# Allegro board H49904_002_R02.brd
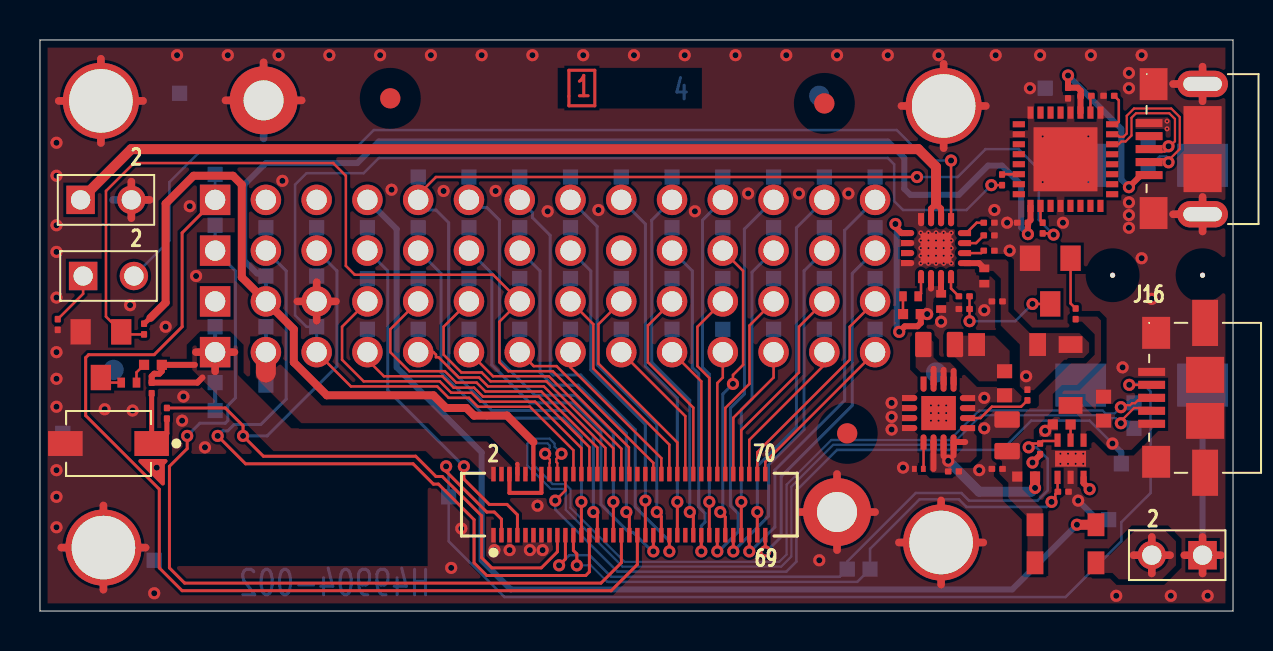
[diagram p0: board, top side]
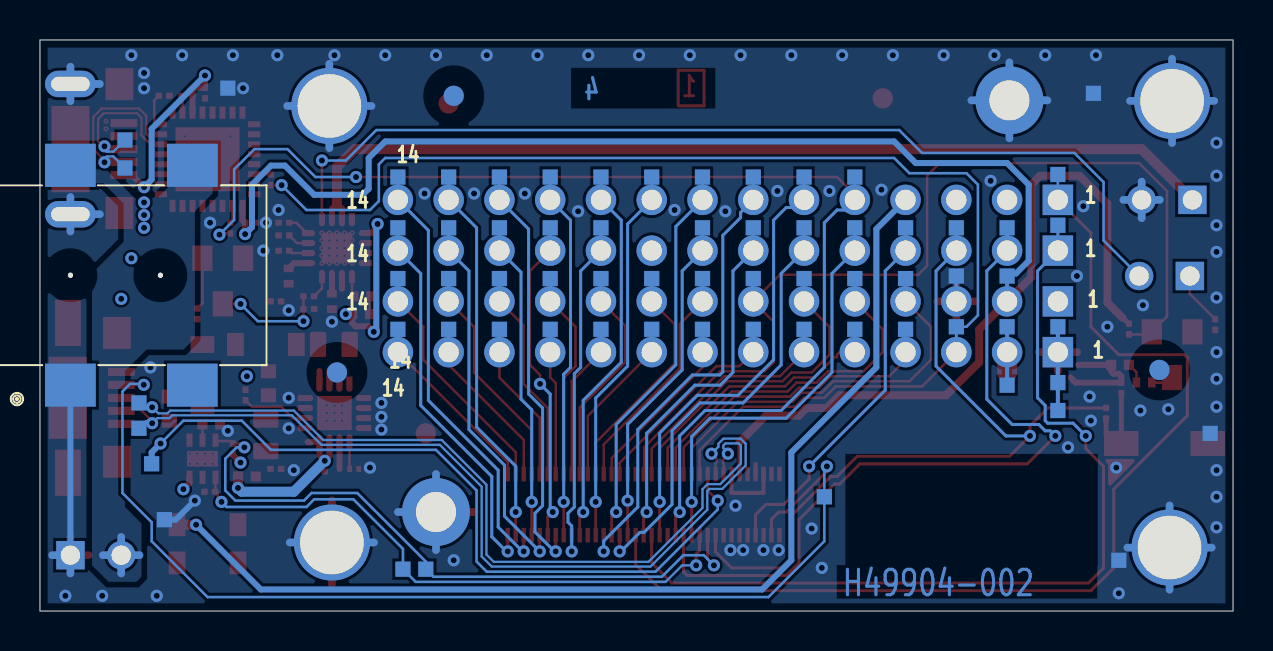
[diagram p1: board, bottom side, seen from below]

Outline 59.69 x 28.57 mm; copper layers: TOP, PWR_GND, GND, BOTTOM. Coordinates in mm from the lower left corner of the outline.
Outline path: 0,28.57 0,0 59.69,0 59.69,28.57 0,28.57

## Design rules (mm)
constraint set DEFAULT: min track width 0.127
net group USB_D: nets USB_DN USB_DP
net group USBD: nets N11374 N11378
net group PWR_GND: nets 5V VBUS_2 VIN

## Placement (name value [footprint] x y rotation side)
C1  22UF  [SMC0603_HI_VALUE]  48.26 12 0 top
C3  0.1uF  [C0201]  45.97 6.99 270 top
C4  33000pF  [SMC0201]  44.2 7.11 270 top
C5  10uF  [SMC0402]  45.09 15.88 0 top
C6  0.1uF  [C0201]  47.62 15.49 90 top
C8  10uF  [SMC0402]  47.24 17.14 0 top
C9  0.1uF  [C0201]  51.44 25.65 180 top
C10  0.1uF  [C0201]  48.9 19.43 90 top
C36  2.2uF  [SMC0603_HI_VALUE]  53.21 9.53 180 top
C47  10uF  [SMC0805]  48.39 8 180 top
C48  0.1uF  [C0201]  53.21 25.78 90 top
CR1  RB160M-40  [SOD123_67X106]  51.56 13.34 0 top
CR2  D2BW319000  [SCR_27X17MA]  48.39 13.34 270 top
CR6  D2BW319000  [SCR_27X17MA]  51.31 4.32 90 top
CR7  D2BW319000  [SCR_27X17MA]  51.31 2.41 90 top
DS1  GREEN  [SMLED0402]  4.06 11.43 90 top
DS3  GREEN  [SMLED0402]  43.94 15.75 270 top
J1  CON2_HDR  [102276-001]  2.16 16.76 90 top
J2  CON2_HDR  [102276-001]  2.03 20.57 90 top
J3  G58911-001  [RCPT_USB_5P_DIP_SM]  58.17 23.11 90 top
J7  70Pin BTB  Socket HIROSE DF40  [2X35_P4MM_BTB_AXT_SKT_MB]  22.69 3.8 0 top
J16  E77884-001  [RCPT_USB_5P_6MTG_SM]  58.29 10.67 90 top
J17  1x14  [1X14RCPT_2P54_VT_TH]  6.22 20.57 0 top
J18  1x14  [1X14RCPT_2P54_VT_TH]  6.22 18.03 0 top
J19  1x14  [1X14RCPT_2P54_VT_TH]  6.22 15.49 0 top
J20  1x14  [1X14RCPT_2P54_VT_TH]  6.22 12.95 0 top
J21  CON2_HDR  [102276-001]  58.17 2.79 270 top
J22  DC_JACK_SMT  [DC_PWR_JACK_SM_14P8X9MM]  58.17 11.3 90 bottom
L1  1uH  [SML0805]  44.2 13.34 90 top
MGT5  NPTH125  [SYMBOL_NPTH125]  45.09 3.43 0 top
MTG1  -  [NPIN787]  11.19 25.55 0 top
MTG2  -  [NPIN787]  39.88 4.95 0 top
MTG3  NPTH125  [SYMBOL_NPTH125]  3.05 25.53 0 top
MTG4  NPTH125  [SYMBOL_NPTH125]  45.21 25.27 0 top
MTG6  NPTH125  [SYMBOL_NPTH125]  3.17 3.17 0 top
NOREF  -  [unnamed]  39.24 25.4 0 top
NOREF#2  -  [#2]  0 27.75 0 top
NOREF#3  -  [#2]  3.17 3.17 0 top
NOREF#4  -  [unnamed]  40.39 8.89 0 top
NOREF#5  -  [#2]  1.73 0 90 top
NOREF#6  -  [unnamed]  17.53 25.65 0 top
NOREF#7  -  [#2]  3.17 3.17 0 top
NOREF#8  -  [unnamed]  38.99 25.78 180 bottom
NOREF#9  -  [unnamed]  3.68 12.06 180 bottom
NOREF#10  -  [unnamed]  44.83 11.94 180 bottom
Q2  BSS138  [SOT23]  51.56 17.65 270 top
Q8  BSS138  [SOT23]  4.06 13.97 270 top
R2  0R  [R0201]  49.4 10.54 180 top
R4  1K  [R0201]  51.82 14.61 180 top
R5  1.62K  [R0201]  46.51 15.75 270 top
R6  1.62K  [R0201]  45.97 15.11 90 top
R7  0R  [R0201]  48.13 21.84 0 top
R8  0R  [R0201]  52.07 25.78 90 top
R9  0R  [R0201]  50.16 19.43 0 top
R36  10K  [SMR0201]  50.04 8.38 0 top
R37  100K  [SMR0201]  50.93 5.97 90 top
R38  576  [SMR0402]  51.56 9.33 270 top
R39  4.7K  [SMR0201]  47.75 19.43 270 top
R48  10K  [SMR0201]  5.59 11.43 0 top
R49  220  [SMR0201]  6.35 10.16 0 top
R72  2K  [SMR0201]  47.75 18.8 270 top
R85  10K  [SMR0201]  5.21 13.84 180 top
R86  576  [SMR0402]  5.21 12.32 90 top
R111  47K  [SMR0201]  47.75 18.03 270 top
R114  576  [SMR0402]  43.18 14.86 90 top
R115  100mOhm  [SMR0402]  48.9 6.73 90 top
R116  10K  [SMR0201]  0.89 14.61 0 top
R117  10K  [SMR0201]  47.62 7.11 90 top
SW1  LIGHT TOUCH SWITCH EVQP7J01P  [SSW2RPB]  3.43 8.38 270 top
TP1  30 MIL TESTPAD  [TP30S]  8.76 11.43 180 bottom
TP2  30 MIL TESTPAD  [TP30S]  50.29 26.16 180 bottom
TP3  30 MIL TESTPAD  [TP30S]  8.76 14.22 180 bottom
TP4  30 MIL TESTPAD  [TP30S]  20.45 5.71 180 bottom
TP5  30 MIL TESTPAD  [TP30S]  8.76 10.03 180 bottom
TP6  30 MIL TESTPAD  [TP30S]  1.14 8.89 180 bottom
TP7  30 MIL TESTPAD  [TP30S]  11.3 11.3 180 bottom
TP8  30 MIL TESTPAD  [TP30S]  16.38 19.18 180 bottom
TP9  30 MIL TESTPAD  [TP30S]  11.3 14.22 180 bottom
TP10  30 MIL TESTPAD  [TP30S]  5.71 2.54 180 bottom
TP11  30 MIL TESTPAD  [TP30S]  11.3 16.76 180 bottom
TP12  30 MIL TESTPAD  [TP30S]  6.99 25.91 180 bottom
TP13  30 MIL TESTPAD  [TP30S]  53.47 4.57 180 bottom
TP14  30 MIL TESTPAD  [TP30S]  54.74 10.41 180 bottom
TP15  30 MIL TESTPAD  [TP30S]  13.84 16.76 180 bottom
TP16  30 MIL TESTPAD  [TP30S]  54.74 9.14 180 bottom
TP17  30 MIL TESTPAD  [TP30S]  13.84 19.18 180 bottom
TP18  30 MIL TESTPAD  [TP30S]  54.1 7.37 180 bottom
TP19  30 MIL TESTPAD  [TP30S]  40.39 2.1 180 bottom
TP20  30 MIL TESTPAD  [TP30S]  13.84 14.22 180 bottom
TP21  30 MIL TESTPAD  [TP30S#2]  41.53 1.33 180 bottom
TP22  30 MIL TESTPAD  [TP30S]  16.38 16.64 180 bottom
TP23  30 MIL TESTPAD  [TP30S]  18.92 19.18 180 bottom
TP24  30 MIL TESTPAD  [TP30S]  16.38 14.1 180 bottom
TP25  30 MIL TESTPAD  [TP30S]  11.3 19.18 180 bottom
TP26  30 MIL TESTPAD  [TP30S]  18.92 16.64 180 bottom
TP27  30 MIL TESTPAD  [TP30S]  18.92 21.72 180 bottom
TP28  30 MIL TESTPAD  [TP30S]  18.92 14.1 180 bottom
TP29  30 MIL TESTPAD  [TP30S]  21.46 16.64 180 bottom
TP30  30 MIL TESTPAD  [TP30S]  21.46 21.72 180 bottom
TP31  30 MIL TESTPAD  [TP30S]  21.46 14.1 180 bottom
TP32  30 MIL TESTPAD  [TP30S]  8.76 19.3 180 bottom
TP33  30 MIL TESTPAD  [TP30S]  24 16.64 180 bottom
TP34  30 MIL TESTPAD  [TP30S]  24 19.18 180 bottom
TP35  30 MIL TESTPAD  [TP30S]  8.76 21.84 180 bottom
TP36  30 MIL TESTPAD  [TP30S]  26.54 19.18 180 bottom
TP37  30 MIL TESTPAD  [TP30S]  21.46 19.18 180 bottom
TP38  30 MIL TESTPAD  [TP30S]  26.54 21.72 180 bottom
TP39  30 MIL TESTPAD  [TP30S]  26.54 16.64 180 bottom
TP40  30 MIL TESTPAD  [TP30S]  24 21.72 180 bottom
TP41  30 MIL TESTPAD  [TP30S]  29.08 16.64 180 bottom
TP42  30 MIL TESTPAD  [TP30S]  29.08 21.72 180 bottom
TP43  30 MIL TESTPAD  [TP30S]  29.08 14.1 180 bottom
TP44  30 MIL TESTPAD  [TP30S]  31.62 16.64 180 bottom
TP45  30 MIL TESTPAD  [TP30S]  31.62 21.72 180 bottom
TP46  30 MIL TESTPAD  [TP30S]  31.62 14.1 180 bottom
TP47  30 MIL TESTPAD  [TP30S]  31.62 19.18 180 bottom
TP48  30 MIL TESTPAD  [TP30S]  34.16 16.64 180 bottom
TP49  30 MIL TESTPAD  [TP30S]  34.16 21.72 180 bottom
TP50  30 MIL TESTPAD  [TP30S]  34.16 14.1 180 bottom
TP51  30 MIL TESTPAD  [TP30S]  36.7 21.72 180 bottom
TP52  30 MIL TESTPAD  [TP30S]  36.7 16.64 180 bottom
TP53  30 MIL TESTPAD  [TP30S]  34.16 19.18 180 bottom
TP54  30 MIL TESTPAD  [TP30S]  36.7 14.1 180 bottom
TP55  30 MIL TESTPAD  [TP30S]  39.24 19.18 180 bottom
TP56  30 MIL TESTPAD  [TP30S]  39.24 16.64 180 bottom
TP57  30 MIL TESTPAD  [TP30S]  36.7 19.18 180 bottom
TP58  30 MIL TESTPAD  [TP30S]  39.24 14.1 180 bottom
TP59  30 MIL TESTPAD  [TP30S]  41.78 21.72 180 bottom
TP60  30 MIL TESTPAD  [TP30S]  41.78 16.64 180 bottom
TP61  30 MIL TESTPAD  [TP30S]  39.24 21.72 180 bottom
TP62  30 MIL TESTPAD  [TP30S]  41.78 14.1 180 bottom
TP63  30 MIL TESTPAD  [TP30S]  41.78 19.18 180 bottom
TP85  30 MIL TESTPAD  [TP30S]  55.44 22.17 0 bottom
TP86  30 MIL TESTPAD  [TP30S]  55.44 23.57 0 bottom
TP87  30 MIL TESTPAD  [TP30S]  26.54 14.1 180 bottom
TP88  30 MIL TESTPAD  [TP30S]  24 14.1 180 bottom
U1  BQ24074  [LCC16_3X3MM_EP61]  44.83 18.16 270 top
U2  FT232R  [LCC32_P5MM_3P2SQ_NONC]  51.31 22.61 90 top
U36  MIC2039  [DFN6P_65M_2X2M]  51.56 7.62 270 top
U37  TPS62133  [LCC16_3X3MM_67DIE_39H]  44.96 9.91 270 top

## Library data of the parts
C1 = CAPC,X5R,0603,6.3V,20%,22UF
C3 C6 C9 C10 C48 = CAP
C4 = CAPC,X5R,0201,6.3V,10%,33000pF
C5 C8 = CAPC,X5R,0402,6.3V,20%,10uF: tolerance: 20%
C36 = CAPC,X5R,0603,25V,10%,2.2uF: tolerance: 10%; room: USB
C47 = CAPC,X7R,0805,50V,10%,1.0uF: tolerance: 10%
CR1 = DIO,SHTKY,SOD123,RB160M-40
CR2 CR6 CR7 = DIO,SHTKY,DB2W319000L
DS1 DS3 = LED,SMT,GREEN,V,0402
J1 J2 J21 = CON2,HDR,TH,0.1in,A91829-020
J3 J16 = CON4,USB,RA,_1
J7 = CON70,SKT,SM,4mm,AXT570124_0: room: NO_ROOM
J17-J20 = CON14,1X14,0.1,0.093: room: NO_ROOM
J22 = CON3,Pwr-Jack,SMT,KLDX-2mm
L1 = INDCT,1uH,1.1A,30%,0805: tolerance: 30%; room: NO_ROOM
MGT5 MTG3 MTG4 MTG6 = symbol_npth125_0
MTG1 MTG2 = MOUNTING HOLE 787
Q2 Q8 = XSTR,BSS138,FET,NCH,SOT23
R2 R7-R9 = R_0
R4-R6 = R0603
R36 R85 R116 R117 = RESD,0201,5%,1/20W,10K: tolerance: 5%; room: AUDIO_CODEC
R37 = RESD,0201,5%,1/20W,100K: tolerance: 5%; room: APE_PMIC_MISC
R38 R86 R114 = RESD,0201,1%,1/20W,562: tolerance: 1%
R39 = RESD,0201,5%,1/20W,4.7K: tolerance: 5%; room: APE_PMIC_MISC
R48 = RESD,0201,5%,1/20W,10K: tolerance: 5%; room: USB
R49 = RESD,0201,5%,1/20W,220: tolerance: 5%; room: UI_BUTTONS
R72 = RESD,0201,1%,1/20W,2K: tolerance: 1%; room: APE_PMIC_MISC
R111 = RESD,0201,1%,1/20W,47K: tolerance: 1%
R115 = RESD,0402,1%,1/16W,100mOhm: tolerance: 1%
SW1 = SWITCH,EVQP7J01P,4P,PWR_0: room: UI_BUTTONS
TP1-TP63 TP85-TP88 = TestPad,C80,SMT: room: TEST_APE
U1 = IC,BQ24232,QFN16,USB_CHGR
U2 = FT232R_0
U36 = IC,MIC2039,UsbPwrSwtch_0: User Part Number: H40907-001; Tolerance: XXX; room: NO_ROOM
U37 = TPS62133_0

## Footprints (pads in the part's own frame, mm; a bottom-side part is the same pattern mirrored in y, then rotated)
1X14RCPT_2P54_VT_TH
  rect 1.524x1.524 hole 1.016: 1(2.54,0)
  round 1.524 hole 1.016: 2(5.08,0) 3(7.62,0) 4(10.16,0) 5(12.7,0) 6(15.24,0) 7(17.78,0) 8(20.32,0) 9(22.86,0) 10(25.4,0) 11(27.94,0) 12(30.48,0) 13(33.02,0) 14(35.56,0)
2X35_P4MM_BTB_AXT_SKT_MB
  rect 0.22x0.728 smd: 1(0,0) 2(0,3.058) 3(0.4,0) 4(0.4,3.058) 5(0.8,0) 6(0.8,3.058) 7(1.2,0) 8(1.2,3.058) 9(1.6,0) 10(1.6,3.058) 11(2,0) 12(2,3.058) 13(2.4,0) 14(2.4,3.058) 15(2.8,0) 16(2.8,3.058) 17(3.2,0) 18(3.2,3.058) 19(3.6,0) 20(3.6,3.058) 21(4,0) 22(4,3.058) 23(4.4,0) 24(4.4,3.058) 25(4.8,0) 26(4.8,3.058) 27(5.2,0) 28(5.2,3.058) 29(5.6,0) 30(5.6,3.058) 31(6,0) 32(6,3.058) 33(6.4,0) 34(6.4,3.058) 35(6.8,0) 36(6.8,3.058) 37(7.2,0) 38(7.2,3.058) 39(7.6,0) 40(7.6,3.058) 41(8,0) 42(8,3.058) 43(8.4,0) 44(8.4,3.058) 45(8.8,0) 46(8.8,3.058) 47(9.2,0) 48(9.2,3.058) 49(9.6,0) 50(9.6,3.058) 51(10,0) 52(10,3.058) 53(10.4,0) 54(10.4,3.058) 55(10.8,0) 56(10.8,3.058) 57(11.2,0) 58(11.2,3.058) 59(11.6,0) 60(11.6,3.058) 61(12,0) 62(12,3.058) 63(12.4,0) 64(12.4,3.058) 65(12.8,0) 66(12.8,3.058) 67(13.2,0) 68(13.2,3.058) 69(13.6,0) 70(13.6,3.058)
102276-001
  rect 1.422x1.422 hole 0.965: 1(0,0)
  round 1.422 hole 0.965: 2(0,-2.54)
C0201
  custom 0.076x0.076 smd: 1(0,0) 2(0,-0.533)
DC_PWR_JACK_SM_14P8X9MM
  round 0.254 hole 1.803 unplated: (5.5,-4.5)
  round 0.254 hole 1.6 unplated: (5.501,0)
  rect 2.159x2.54 smd: 1(0,0) 2(0,-6.1) 3(11,0) 4(11,-6.1)
DFN6P_65M_2X2M
  rect 0.66x0.305 smd: 1(-0.93,0.65) 2(-0.93,0) 3(-0.93,-0.65) 4(0.93,-0.65) 5(0.93,0) 6(0.93,0.65)
  rect 0.787x1.549 smd: 7(0,0)
LCC16_3X3MM_67DIE_39H
  custom 0.076x0.076 smd: 1(-1.448,0.752) 2(-1.448,0.252) 3(-1.448,-0.249) 4(-1.448,-0.749) 5(-0.752,-1.448) 6(-0.252,-1.448) 7(0.249,-1.448) 8(0.749,-1.448) 9(1.448,-0.752) 10(1.448,-0.252) 11(1.448,0.249) 12(1.448,0.749) 13(0.752,1.448) 14(0.252,1.448) 15(-0.249,1.448) 16(-0.749,1.448)
  rect 1.702x1.702 smd: 17(0,0)
LCC16_3X3MM_EP61
  custom 0.076x0.076 smd: 1(-1.422,0.752) 2(-1.422,0.252) 3(-1.422,-0.249) 4(-1.422,-0.749) 5(-0.752,-1.422) 6(-0.252,-1.422) 7(0.249,-1.422) 8(0.749,-1.422) 9(1.422,-0.752) 10(1.422,-0.252) 11(1.422,0.249) 12(1.422,0.749) 13(0.752,1.422) 14(0.252,1.422) 15(-0.249,1.422) 16(-0.749,1.422)
  rect 1.549x1.549 smd: 17(0,0)
LCC32_P5MM_3P2SQ_NONC
  rect 0.61x0.305 smd: 1(-2.334,1.75) 2(-2.334,1.25) 3(-2.334,0.749) 4(-2.334,0.252) 5(-2.334,-0.249) 6(-2.334,-0.749) 7(-2.334,-1.25) 8(-2.334,-1.75) 17(2.334,-1.75) 18(2.334,-1.25) 19(2.334,-0.749) 20(2.334,-0.252) 21(2.334,0.249) 22(2.334,0.749) 23(2.334,1.25) 24(2.334,1.75)
  rect 0.305x0.61 smd: 9(-1.75,-2.334) 10(-1.25,-2.334) 11(-0.749,-2.334) 12(-0.252,-2.334) 13(0.249,-2.334) 14(0.749,-2.334) 15(1.25,-2.334) 16(1.75,-2.334) 25(1.75,2.334) 26(1.25,2.334) 27(0.749,2.334) 28(0.252,2.334) 29(-0.249,2.334) 30(-0.749,2.334) 31(-1.25,2.334) 32(-1.75,2.334)
  rect 3.2x3.2 smd: 33(0,0)
NPIN787
  round 3.4 hole 2: 1(0,0)
R0201
  custom 0.076x0.076 smd: 1(0,0) 2(0,-0.533)
RCPT_USB_5P_6MTG_SM
  rect 0.406x1.346 smd: 1(-1.3,2.675) 2(-0.65,2.675) 3(0,2.675) 4(0.65,2.675) 5(1.3,2.675)
  rect 1.803x1.905 smd: MT1(-1.15,0) MT2(1.15,0)
  rect 2.311x1.295 smd: MT3(-3.75,0) MT4(3.75,0)
  rect 1.6x1.397 smd: MT5(-3.2,2.45) MT6(3.25,2.45)
RCPT_USB_5P_DIP_SM
  rect 0.406x1.346 smd: 1(-1.3,2.675) 2(-0.65,2.675) 3(0,2.675) 4(0.65,2.675) 5(1.3,2.675)
  rect 1.905x1.905 smd: MT1(-1.201,0) MT2(1.201,0)
  oval 1.321x2.54 hole 0.711x1.93: MT3(-3.26,0) MT4(3.26,0)
  rect 1.6x1.397 smd: MT5(-3.2,2.45) MT6(3.25,2.45)
SCR_27X17MA
  rect 1.143x0.838 smd: 1(0,1.525) 2(0,-1.525)
SMC0201
  custom 0.06x0.06 smd: 1(0,0) 2(0,-0.451)
SMC0402
  custom 0.095x0.095 smd: 1(0,0) 2(0,-0.766)
SMC0603_HI_VALUE
  custom 0.175x0.175 smd: 1(0,0) 2(0,-1.204)
SMC0805
  custom 0.204x0.204 smd: 1(0,0) 2(0,-1.581)
SML0805
  custom 0.204x0.204 smd: 1(0,0) 2(0,-1.581)
SMLED0402
  custom 0.095x0.095 smd: 1(0,0) 2(0,-0.766)
SMR0201
  custom 0.076x0.076 smd: 1(0,0) 2(0,-0.533)
SMR0402
  custom 0.127x0.127 smd: 1(0,0) 2(0,-0.889)
SOD123_67X106
  rect 1.194x0.838 smd: 1(0,0) 2(0,-3.048)
SOT23
  custom 0.254x0.254 smd: 1(0,0) 2(0,-2.032) 3(2.286,-1.016)
SSW2RPB
  rect 1.245x1.727 smd: 1(0,2.159) 2(0,-2.159)
SYMBOL_NPTH125
  round 3.81 hole 3.18: 1(0,0)
TP30S
  rect 0.762x0.762 smd: 1(0,0)
TP30S#2
  rect 0.762x0.762 smd: 1(0,0.762)
unnamed
  round 1.016 smd: (0,0)

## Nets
5V: J19.1
5V_SYS: C6.2(END2) C8.1 CR1.1(CATHODE) CR2.1(CATHODE) R2.2 U1.13(IN) U36.6(VIN)
GND: C1.2 C3.1(END1) C4.2 C5.2 C6.1(END1) C8.2 C9.1(END1) C10.1(END1) C36.2 C47.2 C48.1(END1) J2.2 J3.5(GND) J3.MT1 J3.MT2 J3.MT3 J3.MT4 J3.MT5 J3.MT6 J7.1 J7.5 J7.9 J7.11 J7.13 J7.15 J16.5(GND) J16.MT1 J16.MT2 J16.MT3 J16.MT4 J16.MT5 J16.MT6 J19.3 J21.1 J22.1(GND) MGT5.1 MTG1.1 MTG2.1 MTG3.1 MTG4.1 MTG6.1 Q2.2(S) Q8.2(S) R6.1 R37.2 R38.2 R39.1 R72.1 R111.1 R116.2 R117.1 SW1.2(B) TP2.1 TP6.1 TP10.1 TP12.1 TP13.1 TP15.1 U1.4(C\E\) U1.6(EN1) U1.8(VSS) U1.17(TPAD) U2.4(GND3) U2.17(GND1) U2.20(GND2) U2.24(AGND) U2.26(TEST) U2.33(TPAD) U36.5(GND) U36.7(TPAD) U37.5(FB) U37.6(AGND) U37.7(FSW) U37.8(DEF) U37.15(PGND1) U37.16(PGND2) U37.17(THPAD)
VBUS: C36.1 CR1.2(ANODE) J7.20 J16.1(VCC) TP18.1 U36.1(VOUT)
VBUS_2: C9.2(END2) J3.1(VCC) R8.1 U2.19(VCC)
VIN: CR6.2(ANODE) J17.4
FAULT: J7.19 R36.1 TP19.1 U36.3(F\A\U\L\T\)
FW_RCVR: J7.69 J18.14 TP63.1
GP12_PWM0: J7.35 J18.7 TP34.1
GP13_PWM1: J7.33 J18.1 TP32.1
GP14: J7.48 J19.9 TP41.1
GP15: J7.42 J20.7 TP88.1
GP19: J7.41 J18.6 TP37.1
GP20: J7.43 J17.8 TP38.1
GP27: J7.45 J17.7 TP40.1
GP28: J7.47 J17.9 TP42.1
GP40: J7.52 J19.10 TP44.1
GP41: J7.54 J20.10 TP46.1
GP42: J7.50 J20.9 TP43.1
GP43: J7.56 J19.11 TP48.1
GP44: J7.24 J19.4 TP22.1
GP45: J7.26 J20.4 TP24.1
GP46: J7.28 J19.5 TP26.1
GP47: J7.30 J20.5 TP28.1
GP48: J7.32 J19.6 TP29.1
GP49: J7.34 J20.6 TP31.1
GP77: J7.60 J19.12 TP52.1
GP78: J7.58 J20.11 TP50.1
GP79: J7.62 J20.12 TP54.1
GP80: J7.66 J20.13 TP58.1
GP81: J7.70 J20.14 TP62.1
GP82: J7.64 J19.13 TP56.1
GP83: J7.68 J19.14 TP60.1
GP84: J7.44 J20.8 TP87.1
GP109: J7.55 J17.11 TP49.1
GP110: J7.53 J18.10 TP47.1
GP111: J7.51 J17.10 TP45.1
GP114: J7.59 J18.11 TP53.1
GP115: J7.57 J17.12 TP51.1
GP128: J7.65 J17.14 TP59.1
GP129: J7.63 J18.12 TP57.1
GP130: J7.61 J18.13 TP55.1
GP131: J7.46 J19.8 TP39.1
GP134: J7.22 J20.3 R7.2 TP20.1
GP135: J7.27 J17.5 R9.2 TP27.1
GP165: J7.25 J18.2 TP25.1
GP182_PWM2: J7.37 J17.1 TP35.1
GP183_PWM3: J7.39 J18.8 TP36.1
GPI_PWRBTN_N: J7.17 J18.3 R49.1 TP17.1
GPI_PWRBTN_N_L: R48.2 R49.2 SW1.1(A)
MSIC_SLPCLK_2: J7.7 J18.4 TP8.1
OSC_CLK_OUT_0: J7.67 J17.13 TP61.1
PSW: J7.21 R37.1 TP21.1 U36.4(EN)
RCVR_MODE: J7.31 J17.6 TP30.1
RESETOUT#: J7.36 J19.7 Q8.1(G) R85.1 TP33.1
USB_DN: J7.18 J16.2(USB-) TP16.1
USB_DP: J7.16 J16.3(USB+) TP14.1
USB_ID: J7.3 J16.4(ID) TP4.1
V_1P80: C10.2(END2) J7.12 J19.2 R36.2 R85.2 TP11.1 U2.1(VCCIO)
V_3P30: J7.8 J7.10 J20.2 TP7.1 TP9.1
V_SYS: C5.1 J7.2 J7.4 J7.6 J7.14 J20.1 R48.1 R86.2 R114.2 TP1.1 TP3.1 TP5.1 U1.5(EN2) U1.10(OUT2) U1.11(OUT1)
V_VBAT_BKUP: J7.23 J18.5 TP23.1
N11374: J3.2(USB-) TP85.1 U2.15(USBDM)
N11378: J3.3(USB+) TP86.1 U2.14(USBDP)
N30036849: R8.2 U2.18(R\E\S\E\T)
N30112835: R38.1 U36.2(ILIM)
N30125838: R7.1 U2.30(TXD)
N30125857: R9.1 U2.2(RXD)
N30202561: DS1.1(LED1) Q8.3(D)
N30202678: DS1.2(LED2) R86.1
N30230113: C48.2(END2) U2.16(3V3OUT)
N30332540: C47.1 CR6.1(CATHODE) CR7.1(CATHODE) R4.1 R115.1 R117.2
N30332593: CR7.2(ANODE) J21.2 J22.3(IN_2) J22.4(IN_1)
N30352182: J2.1 U1.2(BAT1) U1.3(BAT2)
N30352285: DS3.1(LED1) U1.9(\\C\H\R\G\)
N30352331: DS3.2(LED2) R114.1
N30352588: J1.2 U1.1(TS)
N30354262: R39.2 U1.16(ISET)
N30354335: R72.2 U1.15(ITERM)
N30354821: R111.2 U1.14(TMR)
N30354968: Q2.3(D) R5.1 R6.2
N30354976: Q2.1(G) R4.2
N30355044: R5.2 U1.12(ILIM)
N30364668: J1.1 R116.1
N30367578: C3.2(END2) R115.2 U37.10(AVIN) U37.11(PVIN2) U37.12(PVIN1) U37.13(EN)
N30367602: C4.1 U37.9(SS/TR)
N30367634: L1.1 U37.1(SW1) U37.2(SW2) U37.3(SW3)
N30367646: C1.1 CR2.2(ANODE) L1.2
N30367678: R2.1 U37.14(VOS)

Pads without a net: J3 4; J7 29 38 40 49; J17 2 3; J18 9; J22 2; U1 7; U2 3 5 6 7 8 9 10 11 12 13 21 22 23 25 27 28 29 31 32; U37 4

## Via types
v1: diameter 0.61, hole 0.305, TOP to BOTTOM, 143 vias
v2: diameter 0.254, hole 0.102, TOP to PWR_GND, 48 vias

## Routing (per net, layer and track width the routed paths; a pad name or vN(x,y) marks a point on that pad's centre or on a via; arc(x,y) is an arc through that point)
5V_SYS: length 1.8
  TOP w0.3: U1.13 46.98,17.41 C8.1 ; v1(52.51,6.1) 52.21,6.4 U36.6
  vias: v1(49.34,11.75)
GND: length 260.1
  TOP w0.381: 3.05,23.42 MTG3.1 ; MTG3.1 5.16,25.53 ; MTG3.1 3.05,27.64 ; MTG3.1 0.94,25.53 ; 39.88,3.05 MTG2.1 ; MTG2.1 41.78,4.95 ; MTG2.1 39.88,6.86 ; MTG2.1 37.97,4.95 ; 13.84,14.53 J19.3 ; J19.3 12.88,15.49 ; J19.3 13.84,16.46 ; J19.3 14.81,15.49 ; J21.1 58.17,3.71 ; J21.1 58.17,1.88 ; J21.1 59.08,2.79 ; J21.1 57.25,2.79 ; 1.07,3.17 MTG6.1 ; MTG6.1 3.17,1.07 ; MTG6.1 5.28,3.17 ; MTG6.1 3.17,5.28 ; 42.98,3.43 MGT5.1 ; MGT5.1 47.19,3.43 ; MGT5.1 45.09,1.32 ; MGT5.1 45.09,5.54 ; MTG1.1 13.09,25.55 ; MTG1.1 9.28,25.55 ; MTG1.1 11.19,27.46 ; J3.MT3 58.17,20.72 ; J3.MT3 56.69,19.85 ; J3.MT3 58.17,18.99 ; 4.57,19.66 J2.2 ; J2.2 4.57,21.49 ; J2.2 5.49,20.57 ; 45.21,23.16 MTG4.1 ; MTG4.1 43.1,25.27 ; MTG4.1 45.21,27.38 ; MTG4.1 47.32,25.27 ; 58.17,25.51 J3.MT4 ; J3.MT4 56.69,26.37 ; J3.MT4 58.17,27.24
  PWR_GND w0.381: 57.25,2.79 J21.1 ; J21.1 59.08,2.79 ; J21.1 58.17,1.88 ; J21.1 58.17,3.71 ; MTG2.1 39.88,6.66 ; MTG2.1 39.88,3.24 ; MTG2.1 41.59,4.95 ; MTG2.1 38.17,4.95 ; J3.MT3 58.17,20.72 ; J3.MT3 58.17,18.99 ; J3.MT3 56.69,19.85 ; 4.57,19.66 J2.2 ; J2.2 5.49,20.57 ; J2.2 4.57,21.49 ; J2.2 3.66,20.57 ; MTG3.1 5.16,25.53 ; MTG3.1 0.94,25.53 ; MTG3.1 3.05,27.64 ; MTG3.1 3.05,23.42 ; 45.21,23.16 MTG4.1 ; MTG4.1 47.32,25.27 ; MTG4.1 45.21,27.38 ; MTG4.1 43.1,25.27 ; J19.3 13.84,16.46 ; J19.3 12.88,15.49 ; J19.3 14.81,15.49 ; J19.3 13.84,14.53 ; 1.07,3.17 MTG6.1 ; MTG6.1 5.28,3.17 ; MTG6.1 3.17,5.28 ; MTG6.1 3.17,1.07 ; MGT5.1 45.09,5.54 ; MGT5.1 45.09,1.32 ; MGT5.1 42.98,3.43 ; MGT5.1 47.19,3.43 ; J3.MT4 58.17,27.24 ; J3.MT4 56.69,26.37 ; J3.MT4 58.17,25.51 ; MTG1.1 12.9,25.55 ; MTG1.1 9.48,25.55 ; MTG1.1 11.19,23.84 ; MTG1.1 11.19,27.26
  GND w0.381: 3.66,20.57 J2.2 ; J2.2 5.49,20.57 ; J2.2 4.57,19.66 ; J2.2 4.57,21.49 ; MTG1.1 12.9,25.55 ; MTG1.1 11.19,27.26 ; MTG1.1 11.19,23.84 ; MTG1.1 9.48,25.55 ; MGT5.1 45.09,5.54 ; MGT5.1 42.98,3.43 ; MGT5.1 45.09,1.32 ; MGT5.1 47.19,3.43 ; 13.84,14.53 J19.3 ; J19.3 12.88,15.49 ; J19.3 14.81,15.49 ; J19.3 13.84,16.46 ; 0.94,25.53 MTG3.1 ; MTG3.1 3.05,23.42 ; MTG3.1 3.05,27.64 ; MTG3.1 5.16,25.53 ; MTG6.1 3.17,5.28 ; MTG6.1 3.17,1.07 ; MTG6.1 1.07,3.17 ; MTG6.1 5.28,3.17 ; MTG2.1 41.59,4.95 ; MTG2.1 39.88,6.66 ; MTG2.1 39.88,3.24 ; MTG2.1 38.17,4.95 ; 45.21,23.16 MTG4.1 ; MTG4.1 47.32,25.27 ; MTG4.1 43.1,25.27 ; MTG4.1 45.21,27.38 ; 57.25,2.79 J21.1 ; J21.1 59.08,2.79 ; J21.1 58.17,1.88 ; J21.1 58.17,3.71 ; J3.MT3 58.17,20.72 ; J3.MT3 58.17,18.99 ; J3.MT3 56.69,19.85 ; J3.MT4 58.17,27.24 ; J3.MT4 56.69,26.37 ; J3.MT4 58.17,25.51
  BOTTOM w0.2: J19.3 TP15.1
  BOTTOM w0.3: J22.1 J21.1 ; TP13.1 52.9,4.57 v1(51.94,5.52)
  BOTTOM w0.381: 42.98,3.43 MGT5.1 47.19,3.43 ; 3.05,23.42 MTG3.1 ; MTG3.1 3.05,27.64 ; MTG3.1 5.16,25.53 ; MTG3.1 0.94,25.53 ; 45.21,23.16 MTG4.1 ; MTG4.1 43.1,25.27 ; MTG4.1 45.21,27.38 ; MTG4.1 47.32,25.27 ; MTG6.1 5.28,3.17 ; MTG6.1 1.07,3.17 ; MTG6.1 3.17,5.28 ; MTG6.1 3.17,1.07 ; J3.MT4 58.17,27.24 ; J3.MT4 56.69,26.37 ; J3.MT4 58.17,25.51 ; J2.2 5.49,20.57 ; J2.2 3.66,20.57 ; J2.2 4.57,19.66 ; J2.2 4.57,21.49 ; MTG1.1 11.19,27.46 ; MTG1.1 11.19,23.65 ; MTG1.1 13.09,25.55 ; MTG1.1 9.28,25.55 ; 59.08,2.79 J21.1 58.17,1.88 ; MTG2.1 39.88,6.86 ; MTG2.1 39.88,3.05 ; MTG2.1 41.78,4.95 ; 58.17,18.99 J3.MT3 ; J3.MT3 56.69,19.85 ; J3.MT3 58.17,20.72
  vias: v1(0.83,23.43) v1(0.83,21.78) v1(0.83,19.3) v1(0.83,17.97) v1(0.83,15.68) v1(0.83,12.95) v1(0.83,11.62) v1(0.83,10.22) v1(0.83,7.05) v1(0.83,5.71) v1(0.83,4.19) v1(3.24,10.1) v1(4.51,15.3) v1(4.64,10.03) v1(5.71,0.89) v1(5.84,7.18) v1(6.29,14.22) v1(6.86,27.81) v1(7.11,9.53) v1(7.18,10.73) v1(7.49,20.26) v1(7.81,16.76) v1(8.26,8.19) v1(9.4,27.81) v1(11.94,27.81) v1(12.13,21.53) v1(14.48,27.81) v1(17.02,27.81) v1(17.59,21.08) v1(19.56,27.81) v1(20.19,21.02) v1(20.57,2.16) v1(21.08,4.13) v1(22.1,27.81) v1(22.73,3.05) v1(22.8,21.02) v1(23.5,3.05) v1(24.51,3.05) v1(24.64,27.81) v1(24.89,5.27) v1(25.15,3.05) v1(25.4,20) v1(27.18,27.81) v1(27.94,20.07) v1(29.72,27.81) v1(32.26,27.81) v1(32.77,20) v1(34.8,27.81) v1(35.43,20.89) v1(37.34,27.81) v1(37.97,20.89) v1(38.99,2.54) v1(39.88,27.81) v1(40.45,20.89) v1(42.42,27.81) v1(42.61,10.41) v1(42.61,9.72) v1(42.61,9.08) v1(43.18,7.18) v1(44.96,27.81) v1(45.09,14.48) v1(46.99,7.05) v1(47.24,15.05) v1(47.24,10.67) v1(47.24,9.14) v1(47.82,27.81) v1(47.75,20.07) v1(48.39,19.43) v1(48.51,18.03) v1(49.53,26.16) v1(50.04,27.81) v1(50.29,9.02) v1(51.18,19.43) v1(52.58,27.81) v1(53.85,0.76) v1(54.17,12.19) v1(54.48,26.92) v1(54.48,26.16) v1(54.48,20.45) v1(54.48,19.81) v1(54.48,19.18) v1(55.12,27.81) v1(55.12,17.65) v1(55.63,15.62) v1(56.58,0.76) v1(58.42,0.76) v2(44.07,18.92) v2(44.07,18.54) v2(44.07,18.16) v2(44.07,17.78) v2(44.07,17.4) v2(44.45,18.92) v2(44.45,18.54) v2(44.45,18.16) v2(44.45,17.78) v2(44.45,17.4) v2(44.58,10.29) v2(44.58,9.91) v2(44.58,9.53) v2(44.83,18.92) v2(44.83,18.54) v2(44.83,18.16) v2(44.83,17.78) v2(44.83,17.4) v2(44.96,10.29) v2(44.96,9.91) v2(44.96,9.53) v2(45.21,18.92) v2(45.21,18.54) v2(45.21,18.16) v2(45.21,17.78) v2(45.21,17.4) v2(45.34,10.29) v2(45.34,9.91) v2(45.34,9.53) v2(45.59,18.92) v2(45.59,18.54) v2(45.59,18.16) v2(45.59,17.78) v2(45.59,17.4) v2(50.16,23.75) v2(50.16,21.46) v2(51.05,7.87) v2(51.05,7.37) v2(51.44,7.87) v2(51.44,7.37) v2(51.82,7.87) v2(51.82,7.37) v2(52.2,7.87) v2(52.2,7.37) v2(52.45,23.75) v2(52.45,21.46) v2(56.39,24.51) v2(56.39,24.13)
VBUS: length 38
  TOP w0.127: v1(25.78,5.52) 26.29,6.03 J7.20
  BOTTOM w0.127: v1(53.66,8.38) 52.51,9.53 49.59,9.53 48.13,8.06 39.88,8.06 37.85,6.03 37.85,2.48 37.34,1.97 28.89,1.97 25.78,5.08 v1(25.78,5.52)
  BOTTOM w0.3: v1(53.66,8.38) 54.1,7.94 TP18.1
VBUS_2: length 10.5
  TOP w0.3: v1(51.44,26.8) C9.2 51.92,26.19 52.07,26.04 R8.1 52.06,25.77 U2.19 ; J3.1 55.09,21.81 v1(54.48,21.21)
  BOTTOM w0.3: v1(54.48,21.21) 54.1,21.59 54.1,24.13 v1(51.44,26.8)
VIN: length 53.1
  TOP w0.5: CR6.2 v1(51.88,4.32)
  BOTTOM w0.3: J17.4 17.84,19.11 17.84,12.19 22.1,7.94 22.1,2.54 23.56,1.08 48.64,1.08 v1(51.88,4.32)
FAULT: length 33.4
  TOP w0.127: v1(49.47,8.19) 49.66,8.38 R36.1 50.16,8.51 50.87,8.51 U36.3
  TOP w0.15: v1(25.97,2.29) 26.29,2.6 J7.19
  BOTTOM w0.127: v1(49.47,8.19) 49.85,8.19 50.42,7.62 50.42,6.03 49.91,5.52 46.48,5.52 46.1,5.91 43.81,5.91 40.39,2.48 TP19.1 40.01,1.71 28.58,1.71 27.5,2.79 26.48,2.79 v1(25.97,2.29)
FW_RCVR: length 19.3
  TOP w0.15: J7.69 v1(36.29,2.98)
  BOTTOM w0.15: v1(36.29,2.98) 36.35,2.98 37.08,3.72 37.08,6.73 40.64,10.29 40.64,16.89 J18.14 TP63.1
GP12_PWM0: length 18.4
  TOP w0.15: J7.35 29.49,4.8 v1(29.34,4.95)
  BOTTOM w0.15: v1(29.34,4.95) 29.34,8.89 26.92,11.3 25.65,11.3 25.02,11.94 25.02,17.02 J18.7 TP34.1
GP13_PWM1: length 44.4
  TOP w0.15: v1(7.37,8.76) 7.37,8.13 6.48,7.24 6.48,2.16 7.24,1.4 28.07,1.4 29.09,2.42 J7.33
  BOTTOM w0.15: v1(7.37,8.76) 8,9.4 9.27,9.4 9.4,9.53 9.4,10.29 9.78,10.67 9.78,17.02 J18.1 TP32.1
GP14: length 11.9
  TOP w0.127: J7.48 31.89,8.43 27.94,12.38 27.94,14.35 J19.9
  BOTTOM w0.15: TP41.1 J19.9
GP15: length 10.7
  TOP w0.127: J20.7 24.7,12.26 25.84,12.26 30.69,7.41 J7.42
  BOTTOM w0.15: TP88.1 J20.7
GP19: length 22.2
  TOP w0.15: J7.41 v1(30.69,2.98)
  BOTTOM w0.15: v1(30.69,2.98) 30.62,2.98 29.67,3.94 29.46,3.94 28.07,5.33 28.07,9.02 26.67,10.41 24.51,10.41 22.61,12.32 22.61,16.89 J18.6 TP37.1
GP20: length 19.8
  TOP w0.15: v1(30.86,4.95) 31.09,4.73 J7.43
  BOTTOM w0.15: TP38.1 J17.8 27.88,19.24 27.88,12.32 30.86,9.33 v1(30.86,4.95)
GP27: length 23.4
  TOP w0.15: J7.45 v1(31.49,2.98)
  BOTTOM w0.15: TP40.1 J17.7 24.64,19.94 24.64,19.68 25.53,18.8 25.53,11.96 25.68,11.81 27.05,11.81 29.78,9.08 29.78,5.21 31.49,3.5 v1(31.49,2.98)
GP28: length 19.1
  TOP w0.15: J7.47 v1(31.89,5.46)
  BOTTOM w0.15: TP42.1 J17.9 30.29,19.37 30.29,12.26 31.89,10.66 v1(31.89,5.46)
GP40: length 11.2
  TOP w0.127: J7.52 32.69,10.17 30.42,12.45 30.42,14.29 31.62,15.49
  BOTTOM w0.15: TP44.1 31.62,15.49
GP41: length 7.9
  TOP w0.127: J7.54 33.09,11.49 31.62,12.95
  BOTTOM w0.15: 31.62,12.95 TP46.1
GP42: length 8.6
  TOP w0.127: J7.50 32.29,9.75 J20.9
  BOTTOM w0.15: TP43.1 J20.9
GP43: length 10.6
  TOP w0.127: J19.11 32.89,14.22 32.89,12.26 33.49,11.66 J7.56
  BOTTOM w0.15: TP48.1 J19.11
GP44: length 19.7
  TOP w0.127: J7.24 27.09,8.15 24.77,10.48 22.03,10.48 21.59,10.92 20.57,10.92 20,11.49 16.19,11.49 15.11,12.57 15.11,14.22 J19.4
  BOTTOM w0.15: TP22.1 J19.4
GP45: length 15.8
  TOP w0.127: J7.26 27.49,8.2 24.96,10.73 22.16,10.73 21.72,11.18 20.7,11.18 20.13,11.75 17.21,11.75 16.38,12.57 J20.4
  BOTTOM w0.15: J20.4 TP24.1
GP46: length 17.9
  TOP w0.127: J19.5 17.53,14.1 17.53,12.95 18.48,12 20.26,12 20.83,11.43 21.84,11.43 22.29,10.99 25.08,10.99 27.89,8.18 J7.28
  BOTTOM w0.15: TP26.1 J19.5
GP47: length 13.9
  TOP w0.127: J20.5 19.68,12.95 19.81,12.83 19.81,12.7 19.94,12.7 20.95,11.68 21.97,11.68 22.42,11.24 25.21,11.24 28.29,8.16 J7.30
  BOTTOM w0.15: TP28.1 J20.5
GP48: length 16.1
  TOP w0.127: J7.32 28.69,8.14 25.34,11.49 22.54,11.49 22.1,11.94 21.08,11.94 20.19,12.83 20.19,14.22 J19.6
  BOTTOM w0.15: J19.6 TP29.1
GP49: length 12
  TOP w0.127: J20.6 22.67,11.75 25.46,11.75 29.09,8.12 J7.34
  BOTTOM w0.15: J20.6 TP31.1
GP77: length 10.8
  TOP w0.127: J7.60 34.29,10.16 35.5,11.37 35.5,14.29 J19.12
  BOTTOM w0.15: J19.12 TP52.1
GP78: length 7.4
  TOP w0.127: J20.11 34.16,11.68 33.89,11.41 J7.58
  BOTTOM w0.15: TP50.1 J20.11
GP79: length 8.1
  TOP w0.127: J7.62 34.69,9.67 36.7,11.68 J20.12
  BOTTOM w0.15: J20.12 TP54.1
GP80: length 8.8
  TOP w0.127: J7.66 35.49,8.56 39.24,12.32 J20.13
  BOTTOM w0.15: TP58.1 J20.13
GP81: length 9.5
  TOP w0.127: J20.14 36.29,7.46 J7.70
  BOTTOM w0.15: TP62.1 J20.14
GP82: length 11.5
  TOP w0.127: J19.13 37.97,14.22 37.97,11.94 35.09,9.05 J7.64
  BOTTOM w0.15: J19.13 TP56.1
GP83: length 12.2
  TOP w0.127: J7.68 35.89,7.95 40.51,12.57 40.51,14.22 J19.14
  BOTTOM w0.15: J19.14 TP60.1
GP84: length 9.1
  TOP w0.127: J7.44 31.09,7.65 26.54,12.19 J20.8
  BOTTOM w0.15: J20.8 TP87.1
GP109: length 18.5
  TOP w0.15: J7.55 v1(33.49,5.46)
  BOTTOM w0.15: TP49.1 J17.11 33.15,19.56 33.15,12.19 33.49,11.85 v1(33.49,5.46)
GP110: length 17.8
  TOP w0.15: J7.53 v1(33.09,2.98)
  BOTTOM w0.15: TP47.1 31.62,18.03 32.64,17.02 32.64,12.19 32.96,11.87 32.96,5.21 33.27,4.89 33.27,4.45 33.09,4.26 v1(33.09,2.98)
GP111: length 19.2
  TOP w0.15: v1(32.51,4.95) 32.69,4.78 J7.51
  BOTTOM w0.15: TP45.1 31.62,20.57 30.61,19.56 30.61,12.45 32.51,10.54 v1(32.51,4.95)
GP114: length 16.4
  TOP w0.127: J18.11 35.18,17.02 35.18,12.32 34.67,11.81 v1(34.67,11.37)
  TOP w0.15: J7.59 34.29,4.7 v1(34.04,4.95)
  BOTTOM w0.15: v1(34.67,11.37) 34.16,10.86 34.16,5.08 v1(34.04,4.95) ; J18.11 TP53.1
GP115: length 21.1
  TOP w0.15: J7.57 v1(33.89,2.98)
  BOTTOM w0.15: v1(33.89,2.98) 33.95,2.98 34.92,3.96 34.92,4.89 34.54,5.27 34.54,10.16 35.24,10.86 35.24,19.11 J17.12 TP51.1
GP128: length 22.2
  TOP w0.15: J7.65 v1(35.49,2.98)
  BOTTOM w0.15: v1(35.49,2.98) 35.55,2.98 36.77,4.2 36.77,7.05 40.26,10.54 40.26,19.05 J17.14 TP59.1
GP129: length 16.1
  TOP w0.15: J7.63 v1(35.09,5.46)
  BOTTOM w0.15: v1(35.09,5.46) 35.09,10.07 35.62,10.6 35.62,16.95 J18.12 TP57.1
GP130: length 18.9
  TOP w0.15: J7.61 v1(34.69,2.98)
  BOTTOM w0.15: v1(34.69,2.98) 36.45,4.75 36.45,7.3 38.23,9.08 38.23,17.02 J18.13 TP55.1
GP131: length 11.8
  TOP w0.127: J7.46 31.49,8.33 27.69,12.13 27.69,14.35 J19.8
  BOTTOM w0.15: TP39.1 J19.8
GP134: length 63.8
  TOP w0.127: J7.22 26.69,8.05 24.51,10.22 21.91,10.22 21.46,10.67 20.45,10.67 19.88,11.24 15.56,11.24 J20.3 ; R7.2 v1(47.6,21.31)
  BOTTOM w0.127: TP20.1 13.34,14.22 12.76,14.8 12.76,21.34 13.34,21.91 16.19,21.91 16.95,22.67 42.42,22.67 42.74,22.35 42.74,20.51 43.18,20.07 46.35,20.07 v1(47.6,21.31)
  BOTTOM w0.15: TP20.1 J20.3
GP135: length 60.9
  TOP w0.127: v1(50.71,18.83) 50.65,18.9 R9.2 ; v1(43.88,21.72) 19.81,21.72 18.92,20.83 J17.5
  TOP w0.15: J7.27 27.89,4.75 v1(27.69,4.95)
  BOTTOM w0.127: v1(50.71,18.83) 49.97,19.57 49.97,22.1 48.96,23.11 47.31,23.11 45.91,21.72 v1(43.88,21.72)
  BOTTOM w0.15: v1(27.69,4.95) 27.69,8.76 26.42,10.03 22.61,10.03 20.45,12.19 20.45,19.43 19.81,20.07 19.43,20.07 J17.5 TP27.1
GP165: length 37.9
  TOP w0.15: J7.25 27.49,1.96 27.3,1.78 22.35,1.78 21.72,2.41 21.72,4.57 19.94,6.35 19.68,6.35 18.67,7.37 10.29,7.37 v1(8.89,8.76)
  BOTTOM w0.15: v1(8.89,8.76) 9.14,9.02 9.4,9.02 9.72,9.33 11.05,9.33 12.32,10.6 12.32,17.02 J18.2 TP25.1
GP182_PWM2: length 52.2
  TOP w0.15: J7.37 29.89,2.33 28.57,1.02 7.11,1.02 5.97,2.16 5.97,6.1 2.29,9.78 2.29,12.68 2.44,12.83 5.71,12.83 7.11,14.22 7.11,18.92 J17.1
  BOTTOM w0.127: J17.1 TP35.1
GP183_PWM3: length 16.9
  TOP w0.15: J7.39 30.29,5.52 v1(30.29,5.52)
  BOTTOM w0.15: v1(30.29,5.52) 30.29,5.53 30.29,9.34 27.56,12.06 27.56,17.02 J18.8 TP36.1
GPI_PWRBTN_N: length 39
  TOP w0.15: R49.1 9.27,10.16 10.16,9.27 v1(10.16,8.76) 11.18,7.75 18.8,7.75 19.81,6.73 20.13,6.73 22.1,4.76 22.1,2.67 22.61,2.16 25.08,2.16 25.89,2.96 J7.17
  BOTTOM w0.15: TP17.1 J18.3 14.86,17.02 14.86,12.26 11.37,8.76 v1(10.16,8.76)
GPI_PWRBTN_N_L: length 4.2
  TOP w0.25: R49.2 6.35,8.89 5.84,8.38 SW1.1 R48.2
MSIC_SLPCLK_2: length 19
  TOP w0.15: J7.7 23.89,4.81 23.37,5.33 22.48,5.33 21.21,6.6 v1(21.21,7.24)
  BOTTOM w0.15: v1(21.21,7.24) 17.4,11.05 17.4,17.02 J18.4 TP8.1
OSC_CLK_OUT_0: length 19.3
  TOP w0.15: J7.67 v1(35.89,4.95)
  BOTTOM w0.15: TP61.1 J17.13 37.85,19.18 37.85,9.21 35.89,7.25 v1(35.89,4.95)
PSW: length 29.6
  TOP w0.127: v1(50.61,5.46) 50.8,5.65 50.8,5.84 R37.1 50.91,5.98 U36.4
  TOP w0.15: v1(26.86,2.29) 26.86,2.86 26.69,3.03 J7.21
  BOTTOM w0.112: v1(26.86,2.29) 27.56,2.29 28.38,1.46
  BOTTOM w0.127: 28.38,1.46 40.89,1.46 TP21.1 41.53,3.11 44.01,5.59 45.97,5.59 46.35,5.21 50.36,5.21 v1(50.61,5.46)
RCVR_MODE: length 22.4
  TOP w0.15: J7.31 v1(28.69,5.46)
  BOTTOM w0.15: v1(28.69,5.46) 28.69,8.9 26.8,10.79 24.77,10.79 22.99,12.57 22.99,19.56 22.35,20.19 21.84,20.19 J17.6 TP30.1
RESETOUT#: length 49.5
  TOP w0.127: J7.36 29.46,6.88 29.46,8.19 25.65,12 23.43,12 22.99,12.45 22.99,14.48 J19.7 22.67,16.83 15.75,16.83 15.3,17.27 15.3,21.78 14.67,22.42 4.7,22.42 3.3,21.02 3.3,14.73 Q8.1 4.19,13.84 R85.1
  BOTTOM w0.15: TP33.1 J19.7
USB_DN: length 45
  TOP w0.112: v1(26.09,7.87) 25.84,7.62 25.84,7.45 25.89,7.4 J7.18 ; v1(54.08,9.4) 54.08,9.5 54.74,10.16 55.48,10.16 J16.2
  BOTTOM w0.112: TP16.1 54.39,9.49 54.17,9.49 v1(54.08,9.4) 53.82,9.65 53.21,9.65 53.07,9.79 47.09,9.79 45.61,8.32 39.69,8.32 37.59,6.22 37.59,2.73 37.08,2.22 29.15,2.22 26.3,5.06 26.3,6 26.19,6.11 25.56,6.11 24.38,7.28 24.38,8.37 24.64,8.63 25.49,8.63 25.75,8.37 25.75,8.22 v1(26.09,7.87)
USB_DP: length 43.4
  TOP w0.112: J7.16 25.49,7.4 25.51,7.42 25.51,7.58 25.27,7.82 v1(25.27,7.87) ; v1(54.08,10.2) 54.18,10.3 54.54,10.3 54.64,10.4 54.79,10.4 54.93,10.54 55.51,10.54 55.62,10.65 J16.3
  BOTTOM w0.112: v1(25.27,7.87) 25.27,7.93 25.51,8.16 25.51,8.28 25.39,8.39 24.73,8.39 24.62,8.28 24.62,7.38 25.65,6.35 26.29,6.35 26.54,6.1 26.54,5.16 29.25,2.46 36.98,2.46 37.35,2.83 37.35,6.32 39.59,8.56 45.51,8.56 46.99,10.03 53.17,10.03 53.31,9.89 53.77,9.89 v1(54.08,10.2) 54.52,10.2 TP14.1
USB_ID: length 55
  TOP w0.127: J16.4 v1(54.5,11.32)
  TOP w0.15: J7.3 23.09,4.6 22.73,4.95 22.35,4.95 20.32,6.99 v1(20.32,7.24)
  BOTTOM w0.127: v1(54.5,11.32) 54.55,11.37 55.18,11.37 55.56,10.99 55.56,5.91 54.1,4.45 54.1,3.49 51.31,0.7 23.24,0.7 20.45,3.49 TP4.1 20.45,7.11 v1(20.32,7.24)
V_1P80: length 90.1
  TOP w0.2: J7.12 24.69,8.46
  TOP w0.25: 5.52,14.67 R85.2
  TOP w0.3: U2.1 49.56,19.56 C10.2 v1(49.43,18.86) ; v1(49.66,7.43) 50.04,7.81 R36.2
  TOP w0.4: 24.69,8.46 23.37,9.78 21.72,9.78 21.34,10.16 20.32,10.16 19.68,10.79 14.35,10.79 12.7,12.45 12.7,14.1 J19.2 10.1,16.7 10.1,21.34 9.65,21.78 7.68,21.78 6.29,20.38 6.29,15.43 5.52,14.67
  BOTTOM w0.2: TP11.1 J19.2
  BOTTOM w0.3: v1(49.43,18.86) 49.09,19.2 49.09,21.34 48.13,22.29 47.43,22.29 45.97,20.83 43.54,20.83 43.24,21.13 43.24,22.67 42.42,23.5 16.95,23.5 15.88,22.42 11.3,22.42 10.22,21.34 10.22,17.53 10.86,16.89 11.18,16.89 TP11.1
V_3P30: length 4.5
  TOP w0.2: 23.88,7.37 23.89,7.35 J7.8
  TOP w1: J20.2 11.3,11.94
  BOTTOM w0.2: TP7.1 J20.2 TP9.1
V_SYS: length 29.1
  TOP w0.2: 23.49,7.12 J7.6
  TOP w0.203: J7.6 23.49,5.91 25.09,5.91 J7.14
  TOP w0.3: v1(42.99,13.97) 43.27,14.25 43.9,14.25 44.07,14.41 R114.2 v1(44.39,14.86) ; U1.5 43.1,18.91 42.8,19.21 v1(42.8,19.37) ; U1.11 45.08,15.88 C5.1 ; U1.10 44.58,16.13 ; 8.13,11.68 7.87,11.43 R48.1 5.59,11.75 5.71,11.87 5.97,11.87 6.1,12 R86.2 7.75,12.32
  TOP w0.381: 7.8,12.95 J20.1 ; J20.1 8.76,11.99 ; J20.1 9.73,12.95
  PWR_GND w0.381: 8.76,11.99 J20.1 ; J20.1 9.73,12.95 ; J20.1 7.8,12.95
  BOTTOM w0.2: TP5.1 TP1.1 J20.1 TP3.1
  BOTTOM w0.3: v1(42.99,13.97) 42.86,14.1 42.86,19.3 v1(42.8,19.37)
V_VBAT_BKUP: length 21
  TOP w0.15: J7.23 v1(27.09,5.46)
  BOTTOM w0.15: TP23.1 J18.5 20.07,16.89 20.07,11.94 22.35,9.65 26.16,9.65 27.09,8.73 v1(27.09,5.46)
N11374: length 9.8
  TOP w0.112: U2.15 53.88,23.86 54,23.73 54.21,23.73 54.37,23.89 54.37,24.78 54.74,25.15 56.6,25.15 57.02,24.72 57.02,23.11 56.46,22.55 56.46,22.49 ; v1(56.46,22.45) 56.46,22.49 ; 56.46,22.49 56.35,22.61 55.63,22.61 J3.2
  BOTTOM w0.112: v1(56.46,22.45) 56.47,22.47 56.47,22.62 56.35,22.75 56.02,22.75 TP85.1
N11378: length 8.7
  TOP w0.112: J3.3 55.62,22.99 56.27,22.99 56.55,23.27 ; 56.55,23.27 56.47,23.27 v1(56.46,23.26) ; 56.55,23.27 56.78,23.5 56.78,24.62 56.5,24.91 54.84,24.91 54.61,24.68 54.61,23.79 54.31,23.5 54.1,23.5 53.96,23.36 U2.14
  BOTTOM w0.112: v1(56.46,23.26) 56.46,23.1 56.35,22.99 56.02,22.99 TP86.1
N30036849: length 0.9
  TOP w0.127: R8.2 52.56,25.74 U2.18
N30112835: length 0.8
  TOP w0.127: U36.2 R38.1
N30125838: length 0.8
  TOP w0.127: R7.1 48.15,21.86 U2.30
N30125857: length 0.9
  TOP w0.127: U2.2 50.06,19.54 R9.1
N30202561: length 1.1
  TOP w0.127: Q8.3 3.3,11.43 DS1.1
N30202678: length 1
  TOP w0.127: R86.1 4.83,11.94 DS1.2
N30230113: length 1.8
  TOP w0.127: C48.2 53.98,25.55 53.98,24.48 53.85,24.36 U2.16
N30332593: length 7.3
  TOP w0.381: 54.71,2.79 J21.2 ; J21.2 56.54,2.79 ; J21.2 55.63,3.71 ; J21.2 55.63,1.88
  BOTTOM w0.381: J21.2 55.63,3.71 ; J21.2 55.63,1.88 ; J21.2 56.54,2.79 ; J21.2 54.71,2.79
N30352182: length 47.9
  TOP w0.3: U1.3 44.58,20.13 44.83,20.38 45.08,20.13 U1.2
  TOP w0.5: 44.83,20.38 44.83,22.23 43.94,23.11 4.57,23.11 J2.1
N30352285: length 1
  TOP w0.127: U1.9 44.08,15.89 DS3.1
N30352331: length 0.9
  TOP w0.127: DS3.2 43.18,14.86 R114.1
N30352588: length 49.2
  TOP w0.127: U1.1 v1(45.58,22.54)
  BOTTOM w0.127: v1(45.58,22.54) 44.39,22.54 42.86,24.07 16.7,24.07 15.56,22.92 7.94,22.92 6.48,21.46 6.48,18.54 J1.2
N30354262: length 1.2
  TOP w0.127: R39.2 46.86,19.43 46.34,18.91 U1.16
N30354335: length 1.1
  TOP w0.127: U1.15 46.83,18.41 R72.2
N30354821: length 1
  TOP w0.127: U1.14 47.09,17.91 R111.2
N30354968: length 5.6
  TOP w0.127: R5.1 R6.2 v1(46.51,14.5) ; Q2.3 v1(49.66,15.37)
  BOTTOM w0.127: v1(49.66,15.37) 48.79,14.5 v1(46.51,14.5)
N30354976: length 2.6
  TOP w0.127: R4.2 51.56,15.39 Q2.1
N30355044: length 1.2
  TOP w0.127: R5.2 45.58,16.14 U1.12
N30364668: length 2.7
  TOP w0.127: R116.1 2.16,15.88 J1.1
N30367578: length 8.9
  TOP w0.3: 46.29,8.46 U37.12 45.71,7.79 ; U37.11 45.21,7.75 ; U37.10 44.7,8.46 44.7,7.11
  TOP w0.5: R115.2 v1(49.78,6.16)
  BOTTOM w0.5: v1(49.78,6.16) 49.59,5.97 46.99,5.97 v1(45.44,7.52)
N30367602: length 1.4
  TOP w0.127: U37.9 44.21,7.12 C4.1
N30367634: length 2.1
  TOP w0.3: U37.2 45.21,12.07 ; U37.1 45.71,12.01 ; U37.3 44.71,12.12
N30367678: length 3.4
  TOP w0.127: U37.14 47.06,9.65 47.62,10.22 49.09,10.22 R2.1

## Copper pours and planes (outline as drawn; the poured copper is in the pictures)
5V_SYS on TOP: 47.05,17.59 47.05,17.08 47.12,17.02 47.69,17.02 48.07,16.64 48.07,14.29 49.02,13.34 49.02,11.24 49.21,11.05 49.72,11.05 51.24,12.57 52.13,12.57 52.51,12.95 52.51,13.4 52.01,13.91 49.53,13.91 48.45,14.99 48.45,17.46 48.32,17.59
5V_SYS on PWR_GND: 52.13,6.54 52.13,5.91 53.15,4.89 56.13,4.89 57.4,6.16 57.4,13.46 56.58,14.29 49.78,14.29 48.32,12.83 48.32,10.86 48.64,10.54 50.1,10.54 52.45,12.89 54.61,12.89 55.24,12.26 55.24,7.94 54.17,6.86 52.45,6.86
GND on TOP (solid shape): 45.81,9.05 44.1,9.05 44.1,10.76 45.81,10.76
GND on TOP: 59.31,28.19 59.31,0.38 0.38,0.38 0.38,28.19 ; 16 cut-outs
GND on BOTTOM: 0.38,28.19 0.38,0.38 59.31,0.38 59.31,28.19 ; 42 cut-outs
GND on PWR_GND: 0.38,28.19 0.38,0.38 59.31,0.38 59.31,28.19
GND on GND: 0.38,0.38 0.38,28.19 59.31,28.19 59.31,0.38
VBUS on TOP: 51.18,10.48 51.18,9.91 51.24,9.84 51.88,9.84 52.07,9.65 52.07,8.45 52.32,8.45 52.32,8.95 52.39,9.02 52.58,9.02 53.53,8.06 54.61,8.06 55.75,9.21 55.75,9.53 53.98,9.53 53.78,9.72 53.78,9.78 53.72,9.84 52.64,9.84 51.94,10.54 51.24,10.54
V_1P80 on PWR_GND: 50.16,19.49 48.45,19.49 45.85,16.89 45.85,9.53 48.45,6.92 49.85,6.92 50.42,7.49 50.42,9.21 49.66,9.97 48.58,9.97 47.88,10.67 47.88,13.21 49.53,14.86 50.8,14.86 50.8,18.86
V_3P30 on TOP: 24.38,6.73 24.38,8.26 22.35,10.29 14.1,10.29 11.81,12.57 11.81,13.46 10.79,13.46 10.79,11.68 13.08,9.4 19.43,9.4 20.07,8.76 22.48,8.76 23.88,7.37 23.88,6.86 24,6.73
V_SYS on TOP: 23.62,7.24 22.35,8.51 19.94,8.51 19.3,9.14 12.57,9.14 9.91,11.81 9.91,13.21 9.4,13.72 8.13,13.72 7.62,13.21 7.62,12.06 11.68,8 19.3,8 19.68,7.62 21.46,7.62 22.48,6.6 23.5,6.6 23.62,6.73
V_SYS on TOP: 45.21,16.26 44.45,16.26 44.32,16.13 44.32,15.24 44.2,15.11 43.81,15.11 43.69,14.99 43.69,14.61 44.58,14.61 44.7,14.73 44.7,15.62 44.83,15.75 45.21,15.75
V_SYS on PWR_GND: 40.64,13.72 7.62,13.72 7.62,9.53 8.38,8.76 27.94,8.76 28.19,8.51 40.07,8.51 42.86,11.3 43.75,11.3 44.58,12.13 44.58,15.49 42.42,15.49
N30332540 on TOP: 50.16,2.03 50.16,5.08 49.15,6.1 49.15,8.26 49.4,8.26 49.72,8.57 49.72,9.08 50.67,10.03 50.67,10.86 51.12,11.3 51.88,11.3 53.09,12.51 53.09,14.54 52.9,14.73 51.75,14.73 51.69,14.67 51.69,14.54 51.75,14.48 52.13,14.48 52.77,13.84 52.77,12.83 52.32,12.38 51.56,12.38 49.97,10.79 49.97,10.29 49.85,10.16 49.53,10.16 49.21,9.84 49.21,9.02 48.58,8.38 47.88,8.38 47.88,7.75 48.13,7.49 48.13,7.11 48.01,6.99 48.01,6.86 48.45,6.41 48.45,5.65 49.4,4.7 49.4,2.03
N30332593 on TOP: 52.51,2.79 52.51,2.16 52.77,1.91 53.66,1.91 53.98,1.59 56.13,1.59 56.83,2.29 56.83,3.49 56.32,4 54.74,4 53.53,2.79
N30332593 on BOTTOM: 51.05,23.05 51.05,20.89 51.94,20 51.94,13.65 52.51,13.08 54.36,13.08 55.44,12 55.44,5.21 54.61,4.38 54.61,1.71 54.86,1.46 56.26,1.46 57.09,2.29 57.09,16.89 55.5,18.48 55.5,20.38 56.52,21.4 58.42,21.4 58.55,21.53 58.55,22.86 57.59,22.86 56.83,22.1 56.39,22.1 54.99,20.7 53.78,20.7 53.15,21.34 53.15,22.16 52.26,23.05
N30367578 on TOP: 44.51,7.87 44.51,7.05 44.64,6.92 45.53,6.92 45.59,6.99 45.59,7.24 45.78,7.43 46.55,7.43 46.86,7.75 46.86,8.76 46.74,8.89 46.74,9.27 46.23,9.27 46.16,9.21 46.16,8.13 45.91,7.87
N30367634 on TOP: 43.81,13.59 43.81,12.19 44.07,11.94 45.85,11.94 45.85,12.13 45.53,12.45 44.96,12.45 44.7,12.7 44.7,13.46 44.51,13.65 43.88,13.65
N30367646 on TOP: 45.47,13.72 45.47,13.02 46.99,11.49 48.39,11.49 48.51,11.62 48.51,13.02 47.75,13.78 45.53,13.78

Small or netless copper shapes (teardrops, artwork), in the pictures only: 2 on TOP

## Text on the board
BOTTOM: 4 | H49904-002
Ref Des/Silkscreen Bottom: 1 | 14
User.Comments: UNLESS OTHERWISE SPECIFIED: | 1. DIMENSIONS ARE IN INCHES | 2. BREAK ALL SHARP EDGES | 3. DO NOT SCALE DRAWING | 4. TOLERANCES | ANGLES +/- | DRN BY | CHK BY | ENGR | APVD | SIGNATURE | DATE | SCALE | TITLE | SIZE | DCLC | CLASS CODE | DOCUMENT NUMBER | SHEET | OF | REV
TOP: 1
Ref Des/Silkscreen Top: J16
PWR_GND: 2
GND: 3
DIMENSION: -A- | -B-
PAGE_OUTLINE: THIS DRAWING CONTAINS INFORMATION | WHICH IS THE PROPRIETARY PROPERTY | OF INTEL CORPORATION. THIS DRAWING | IS RECEIVED IN CONFIDENCE AND ITS | CONTENTS MAY NOT BE DISCLOSED WITH- | OUT THE PRIOR WRITTEN CONSENT OF | INTEL CORPORATION. | D | C | B | A | 8 | 7 | 6 | 5 | 4 | 3 | 2 | 1
DISPLAY_BOTTOM: PROCESS FLOW | WAVE & SMT
User.6: A | B
User.7: L | M
User.26: Plug End
User.30: SHEET | TITLE | SCALE 1:1 | LAYER | OF | DOCUMENT NUMBER | REV | H49904-002 | 02 | INTEL | MASTER | EDISON MINI BREAKOUT | 07/21/14
User.31: 4 | DEV,PB,
User.32: LAYER 4 (SECONDARY SIDE) | 4
User.33: LAYER 3 (GND PLANE) | 3
User.34: LAYER 2 (PWR/GND PLANE) | 2
User.35: LAYER 4 (SIGNAL/POWER) | 4
User.36: LAYER 5 (GND PLANE) | 5
User.37: LAYER 1 (PRIMARY SIDE) | 1
User.38: SIZE | INTEL PROPRIETARY INFORMATION | DOCUMENT NUMBER | SHEET | REV | D | G87173-205 | 2 | 02 | SECONDARY SIDE
User.39: jeirvin | 06/09/14 | REV | DESCRIPTION | DFT | REVISIONS | DATE | CHK | APVD | 4 | 6 | 9 | 5 | 01 | INITIAL RELEASE | 6   MARK SERIAL NUMBER PER INTEL MARKING STANDARD | 164997 APPROXIMATELY WHERE SHOWN, PRIMARY SIDE. | 7   ONLY SITES OTHER THAN USA & PUERTO RICO SHALL | MARK "MADE IN (COUNTRY OF ORIGIN)" PER INTEL | MARKING STANDARD 164997 APPROXIMATELY WHERE | SHOWN, PRIMARY SIDE. | 8.  SOCKET REFERENCE DESIGNATORS ON ENGINEERING | PARTS LIST ARE THE COMPONENT REFERENCE | DESIGNATORS PREFIXED WITH "X". | 9   MARK PRODUCT CODE PER INTEL MARKING STANDARD | SELECT APPROPRIATE PRODUCT CODE PREFIX PER | SITE POLICY. | 10. PRODUCT CODE IS PER ENGINEERING PARTS LIST. | NOTES: UNLESS OTHERWISE SPECIFIED: | 1.  ITEM IDENTIFICATION NUMBER IS PARENT LINE ITEM | NUMBER ON ENGINEERING PARTS LIST. | 2.  THIS DOCUMENT ALSO EXISTS ON ELECTRONIC MEDIA. | 3.  WORKMANSHIP PER INTEL 99-0007-001. | 4   MARK "PBA" AND ITEM IDENTIFICATION NUMBER PER | INTEL MARKING STANDARD 164997 APPROXIMATELY | WHERE SHOWN, PRIMARY SIDE. | 5   MARK ASSEMBLY VENDOR IDENTIFICATION PER INTEL | SHOWN, SECONDARY SIDE. | 1:1 | H49905-001 | 1 | PBA, EDISON MINI BREAKOUT | PRIMARY SIDE
User.40: LAYER(S) | 1 AND 4 | FINISHED TRACE | WIDTH (MILS) | 4.4 | IMPEDANCE CHART | JEIRVIN | (EDGE TO EDGE) | TRACE SPACING | 5.0 | 06/09/2014 | REQUIRED IMPEDANCE | 90 OHMS | 07/21/14 | TOLERANCE | +/- 10% | REFERENCE | 2 AND 3 | REV | INITIAL RELEASE | DESCRIPTION | W.GILLMER | DFT | REVISIONS | DATE | CHK | APVD | 24 | 9 | 26 | NOTES: UNLESS OTHERWISE SPECIFIED: | 18 V-GROOVE MAY BE LOCATED IN AN AREA +/- 0.010" ON EITHER SIDE OF V-GROOVE CENTERLINE. | 19 V-GROOVE SEPARATION DENOTED BY LINE. | 20 SOLDERMASK MUST NOT EXCEED .001 THICKNESS FROM TOP OF COPPER FEATURE TO TOP OF SOLDERMASK | 21 NO EXPOSED METAL ALLOWED ON TOP SIDE VIA PADS WHERE SHOWN | IN THIS AREA ON TOP SIDE ONLY | 22 NO SOLDERMASK ALLOWED ON SMT PADS | 23 SOLDERMASK MAY ENCROACH ON VIA'S IN ORDER TO CREATE A SOLDERMASK WEB BETWEEN VIA AND PAD. | 17.DELIVERY REQUIREMENTS: | 24. THIEVING ALLOWED ON OUTRIGGERS (BREAKAWAY SECTIONS) BUT NOT ON THE TABS. | 13.FINISH: ENIG | 14.MATERIAL: 370HR OR EQUIVALENT | 26. VENDOR TO MARK MULTIPACK NUMBER APPROXIMATELY WHERE SHOWN. | 15.SOLDERMASK COLOR: BLUE. SILKSCREEN COLOR: WHITE | 10.SMT LAND PATTERNS THAT HAVE A FINISHED PAD WIDTH RANGING FROM | .012 TO .015 MUST USE THE FOLLOWING TOLERANCE, +.002 -.0005. | PB VENDOR TO ADJUST ARTWORK TO COMPENSATE FOR ETCH PROCESS | 11.THIS BOARD REQUIRES VIA CAPPING ON THE SECONDARY SIDE. ALL | VIA CAPPING SHALL FILL 50 TO 90% OF THE HOLE. COVERAGE FOR | ALL VIA IN PAD (VIP) DEVICES SHALL BE 100% PER INTEL | SPECIFICATION 454979. | 12.THESE PADS ARE TO BE COVERED BY SOLDERMASK ON THE PRIMARY AND | SECONDARY SIDES PER THE ARTWORK EXCEPT AS NOTED IN NOTE 16. | 16.ALL PADS MUST NOT BE COVERED BY SOLDERMASK ON THE SECONDARY | 7. COMPARE SUPPLIED IPC-D-356 NETLIST TO SUPPLIED GERBER DATA | PRIOR TO FABRICATION. | SIDE PER THE ARTWORK. | 6. DIMENSIONING AND TOLERANCING PER ANSI Y14.5M. | 25. TOLERANCE OF BOARD OUTLINE AND PANEL  IS +/-0.15 MM (6MILS). | 4  THE CENTER OF THIS HOLE ESTABLISH DATUM -A-. | 5  DATUM -B- IS ESTABLISHED PERPENDICULAR TO DATUM -A- THROUGH | THE CENTER OF THIS HOLE. | 8  THESE HOLES MAY BE PLATED SHUT. | NOTE: THE IMPEDANCE CHARTS WILL REFLECT ALL POSSIBLE | IMPEDANCE VALUES WHICH MAY BE REQUIRED IN THE DESIGN. NOT | ALL VALUES WILL BE PRESENT ON EACH LAYER. | 9  CONTROLLED IMPEDANCE: SEE LAYER STACK AND IMPEDANCE CHART. | 3. FABRICATE PER INTEL SPECIFICATION A84501. | 2. THIS DRAWING ALSO EXISTS ON ELECTRONIC MEDIA. | 1. ITEM IDENTIFICATION NUMBER IS PARENT LINE ITEM NUMBER ON | A. TWO BARE BOARDS (SOLDER SAMPLE) AND CROSS-SECTION SHALL BE | B. A TDR REPORT, ONE PER PANEL SHALL ACCOMPANY THE MATERIAL | ENGINEERING PARTS LIST. | INCLUDED WITH EACH BOARD LOT. | SHIPMENT. | 1:1 | 1 | 02 | PB, EDISON MINI BREAKOUT | H49904-002 | D
User.41: - | SILKSCREEN(SECONDARY) | 1 | DEV,PBA,SSB,
User.42: - | SILKSCREEN (PRIMARY) | 1 | DEV,PB, SST,
User.43: - | SOLDER MASK (SECONDARY) | 1 | DEV,PB,SMB,
User.44: - | SOLDER MASK (PRIMARY) | 1 | DEV,PB,SMT,
User.45: MTG3 | MTG4 | J22 | Plug End | 2.5MM | .06731 | PLANE | SIGNAL | 2.203 | LAYER STACKING | SCALE: NONE | LAYER 4 (0.5 OZ PLATED TO 1.0 OZ) | LAYER 2 (1.0 OZ) | LAYER 3 (1.0 OZ) | LAYER 1 (0.5 OZ PLATED TO 1.0 OZ) | 1. | 1) NPTH locational tolerance = +/-0.05mm from datum | 2) Copper feature to NPTH hole tolerance = +/- 0.10mm. | 3) Unit: mm [inch]. | - | UNLESS OTHERWISE SPECIFIED: | 1. DIMENSIONS ARE IN INCHES | 2. BREAK ALL SHARP EDGES | 3. DO NOT SCALE DRAWING | 4. TOLERANCES | ANGLES +/- | DRN BY | CHK BY | ENGR | APVD | SIGNATURE | DATE | SCALE | TITLE | SIZE | DCLC | CLASS CODE | INTEL PROPRIETARY INFORMATION | DOCUMENT NUMBER | SHEET | OF | REV | SOLDER PASTE (PRIMARY) | SOLDER PASTE (SECONDARY) | 1 | 0.000 | 25.690 | 35.427 | 16.437 | 57.350 | 48.097 | 66.542 | 78.876 | 128.772 | 88.129 | 119.304 | 166.862 | 159.887 | 150.433 | 97.657 | 141.180 | 110.051 | 171.308 | 6.852 | 4.312 | 4.578 | 8x STD FIDUCIALS TOP AND BOTTOM | 2.54 STD ROUTING SLOTS | 3x 3.175 UNPLATED TOOLING HOLES | 4.422 | 6.374 | 7.003 | 16.765 | 26.018 | 47.666 | 56.919 | 66.693 | 78.943 | 88.196 | 109.844 | 119.097 | 129.553 | 128.923 | 135.903 | 140.353 | DEV,PB,SPT, | DEV,PB,SPB, | FIGURE | 12.0 | 38.0 | 40.0 | 78.74 | 125.197 | 63.0 | 71.0 | 76.0x28.0 | 4.0 | DRILL CHART: TOP to BOTTOM | ALL UNITS ARE IN MILS | DRILL CHART: TOP to PWR_GND | TOLERANCE | +0.0/-12.0 | +3.0/-3.0 | +3.15/-3.15 | +2.0/-2.0 | +2.0/-1.0 | +1.0/-4.0 | PLATED | NON-PLATED | QTY | 66 | 77 | 6 | 56 | 2 | 4 | 48 | H49907-002 | PANELIZATION DETAIL | D | G87173-205 | 3 | 02 | PRIMARY SIDE | SECONDARY SIDE
